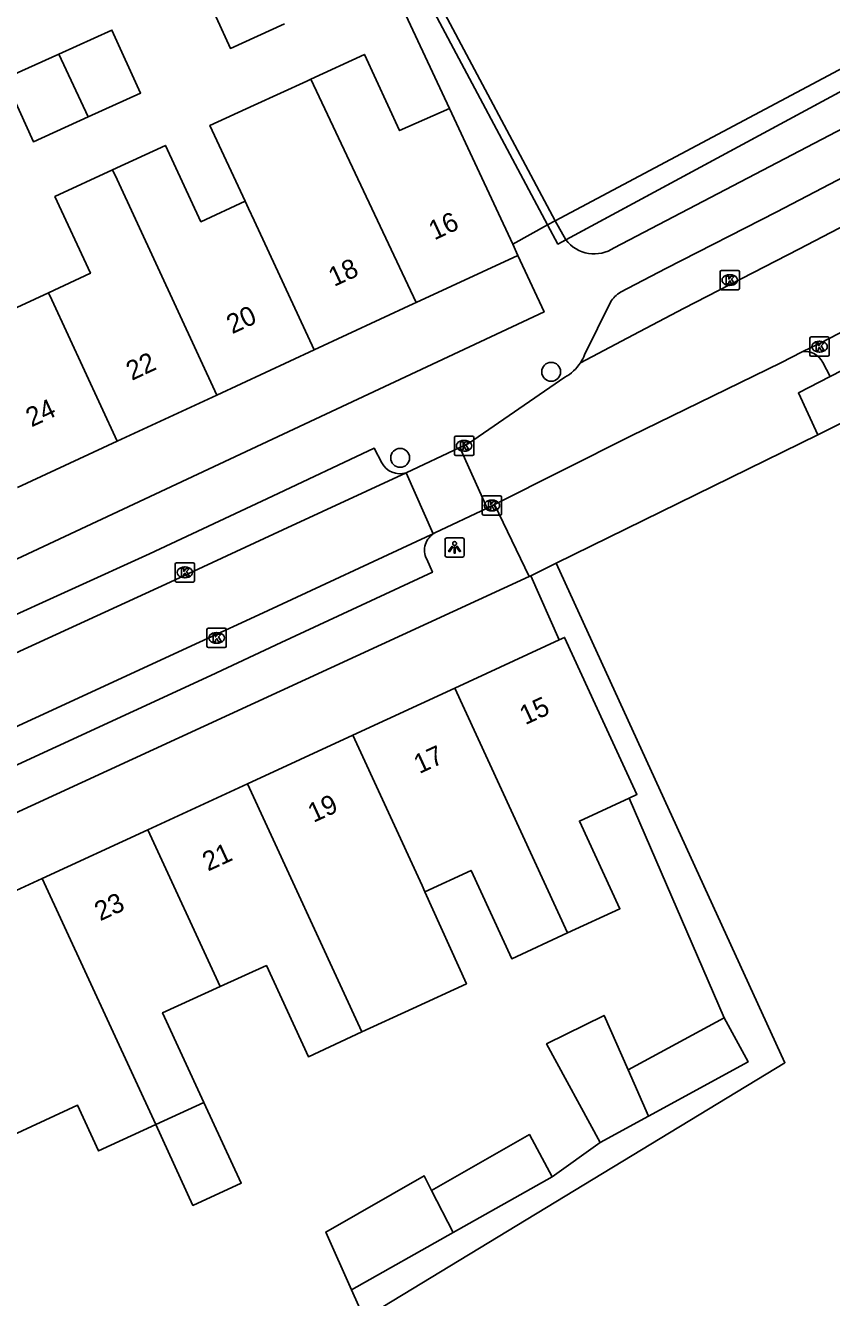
# Model space of a CAD drawing. Extents: x 159265 to 160143, y 383413 to 384319.
# Drawn here: x 159449.6 to 159491.4, y 384178.3 to 384244.2 of the extents above; entities that cross this region are included whole.
import ezdxf

# ---------------------------------------------------------------- set-up
doc = ezdxf.new("R2010")
doc.units = 0
for name, color, linetype in [('IMGEO_Boom', 7, 'Continuous'), ('IMGEO_Haag', 7, 'Continuous'), ('IMGEO_Kolk', 7, 'Continuous'), ('IMGEO_Lichtpunt', 7, 'Continuous'), ('IMGEO_Pand', 7, 'Continuous'), ('IMGEO_Pand_nummerreeks', 7, 'Continuous'), ('IMGEO_Pand_overbouw', 7, 'Continuous'), ('IMGEO_Rijbaan_lokaal_open', 7, 'Continuous'), ('IMGEO_Voetpad_open', 7, 'Continuous')]:
    doc.layers.add(name, color=color, linetype=linetype)

msp = doc.modelspace()

# ---------------------------------------------------------------- linework, layer by layer
at = {"layer": 'IMGEO_Boom'}
for centre in [(159476.832, 384226.238), (159469.003, 384221.78)]:
    msp.add_circle(centre, 0.489, dxfattribs=at)
at = {"layer": 'IMGEO_Haag'}
msp.add_lwpolyline([(159496.545, 384243.294), (159477.587, 384233.071)], dxfattribs=at)
at = {"layer": 'IMGEO_Kolk'}
for p, q in [((159485.589, 384230.564), (159485.589, 384231.416)), ((159485.664, 384231.49), (159486.516, 384231.49)), ((159486.077, 384231.27), (159486.102, 384231.27)), ((159486.59, 384231.416), (159486.59, 384230.564)), ((159486.516, 384230.49), (159485.664, 384230.49)), ((159486.1, 384230.71), (159486.075, 384230.71)), ((159490.239, 384227.116), (159490.239, 384227.968)), ((159490.314, 384228.042), (159491.166, 384228.042)), ((159490.727, 384227.822), (159490.752, 384227.822)), ((159491.24, 384227.968), (159491.24, 384227.116)), ((159490.75, 384227.262), (159490.725, 384227.262)), ((159491.166, 384227.042), (159490.314, 384227.042)), ((159471.82, 384221.979), (159471.82, 384222.831)), ((159471.895, 384222.905), (159472.747, 384222.905)), ((159472.308, 384222.685), (159472.333, 384222.685)), ((159472.821, 384222.831), (159472.821, 384221.979)), ((159472.747, 384221.905), (159471.895, 384221.905)), ((159472.331, 384222.125), (159472.306, 384222.125)), ((159473.335, 384219.811), (159474.187, 384219.811)), ((159473.26, 384218.885), (159473.26, 384219.737)), ((159473.748, 384219.591), (159473.773, 384219.591)), ((159474.261, 384219.737), (159474.261, 384218.885)), ((159474.187, 384218.811), (159473.335, 384218.811)), ((159473.771, 384219.031), (159473.746, 384219.031)), ((159457.346, 384215.419), (159457.346, 384216.271)), ((159457.421, 384216.345), (159458.273, 384216.345)), ((159457.834, 384216.125), (159457.859, 384216.125)), ((159458.347, 384216.271), (159458.347, 384215.419)), ((159458.273, 384215.345), (159457.421, 384215.345)), ((159457.857, 384215.565), (159457.832, 384215.565)), ((159458.993, 384212.026), (159458.993, 384212.878)), ((159459.068, 384212.952), (159459.92, 384212.952)), ((159459.481, 384212.732), (159459.506, 384212.732)), ((159459.994, 384212.878), (159459.994, 384212.026)), ((159459.92, 384211.952), (159459.068, 384211.952)), ((159459.504, 384212.172), (159459.479, 384212.172))]:
    msp.add_line(p, q, dxfattribs=at)
for points in [[(159485.589, 384230.564), (159485.589, 384231.416)], [(159485.664, 384231.49), (159486.516, 384231.49)], [(159485.91, 384231.19), (159486.033, 384231.19), (159486.033, 384231.039), (159486.163, 384231.19), (159486.327, 384231.19), (159486.181, 384231.039), (159486.334, 384230.79), (159486.182, 384230.79), (159486.097, 384230.954), (159486.033, 384230.887), (159486.033, 384230.79), (159485.91, 384230.79), (159485.91, 384231.19)], [(159486.59, 384231.416), (159486.59, 384230.564)], [(159486.516, 384230.49), (159485.664, 384230.49)], [(159490.239, 384227.116), (159490.239, 384227.968)], [(159490.314, 384228.042), (159491.166, 384228.042)], [(159490.56, 384227.742), (159490.683, 384227.742), (159490.683, 384227.591), (159490.813, 384227.742), (159490.977, 384227.742), (159490.831, 384227.591), (159490.984, 384227.342), (159490.832, 384227.342), (159490.747, 384227.506), (159490.683, 384227.439), (159490.683, 384227.342), (159490.56, 384227.342), (159490.56, 384227.742)], [(159491.24, 384227.968), (159491.24, 384227.116)], [(159491.166, 384227.042), (159490.314, 384227.042)], [(159471.82, 384221.979), (159471.82, 384222.831)], [(159471.895, 384222.905), (159472.747, 384222.905)], [(159472.141, 384222.605), (159472.264, 384222.605), (159472.264, 384222.454), (159472.394, 384222.605), (159472.558, 384222.605), (159472.412, 384222.454), (159472.565, 384222.205), (159472.413, 384222.205), (159472.328, 384222.369), (159472.264, 384222.302), (159472.264, 384222.205), (159472.141, 384222.205), (159472.141, 384222.605)], [(159472.821, 384222.831), (159472.821, 384221.979)], [(159472.747, 384221.905), (159471.895, 384221.905)], [(159473.335, 384219.811), (159474.187, 384219.811)], [(159473.26, 384218.885), (159473.26, 384219.737)], [(159473.581, 384219.511), (159473.704, 384219.511), (159473.704, 384219.36), (159473.834, 384219.511), (159473.998, 384219.511), (159473.852, 384219.36), (159474.005, 384219.111), (159473.853, 384219.111), (159473.768, 384219.275), (159473.704, 384219.208), (159473.704, 384219.111), (159473.581, 384219.111), (159473.581, 384219.511)], [(159474.261, 384219.737), (159474.261, 384218.885)], [(159474.187, 384218.811), (159473.335, 384218.811)], [(159457.346, 384215.419), (159457.346, 384216.271)], [(159457.421, 384216.345), (159458.273, 384216.345)], [(159457.667, 384216.045), (159457.79, 384216.045), (159457.79, 384215.894), (159457.92, 384216.045), (159458.084, 384216.045), (159457.938, 384215.894), (159458.091, 384215.645), (159457.939, 384215.645), (159457.854, 384215.809), (159457.79, 384215.742), (159457.79, 384215.645), (159457.667, 384215.645), (159457.667, 384216.045)], [(159458.347, 384216.271), (159458.347, 384215.419)], [(159458.273, 384215.345), (159457.421, 384215.345)], [(159458.993, 384212.026), (159458.993, 384212.878)], [(159459.068, 384212.952), (159459.92, 384212.952)], [(159459.314, 384212.652), (159459.437, 384212.652), (159459.437, 384212.501), (159459.567, 384212.652), (159459.731, 384212.652), (159459.585, 384212.501), (159459.738, 384212.252), (159459.586, 384212.252), (159459.501, 384212.416), (159459.437, 384212.349), (159459.437, 384212.252), (159459.314, 384212.252), (159459.314, 384212.652)], [(159459.994, 384212.878), (159459.994, 384212.026)], [(159459.92, 384211.952), (159459.068, 384211.952)]]:
    msp.add_lwpolyline(points, dxfattribs=at)
for centre, start, end in [((159485.666, 384231.414), 91.55205, 178.44795), ((159485.666, 384231.414), 91.55205, 178.44795), ((159486.514, 384231.414), 1.55205, 88.44795), ((159486.514, 384231.414), 1.55205, 88.44795), ((159485.666, 384230.566), 181.55205, 268.44795), ((159485.666, 384230.566), 181.55205, 268.44795), ((159486.514, 384230.566), 271.55205, 358.44795), ((159486.514, 384230.566), 271.55205, 358.44795), ((159490.316, 384227.966), 91.55205, 178.44795), ((159490.316, 384227.966), 91.55205, 178.44795), ((159491.164, 384227.966), 1.55205, 88.44795), ((159491.164, 384227.966), 1.55205, 88.44795), ((159490.316, 384227.118), 181.55205, 268.44795), ((159490.316, 384227.118), 181.55205, 268.44795), ((159491.164, 384227.118), 271.55205, 358.44795), ((159491.164, 384227.118), 271.55205, 358.44795), ((159471.897, 384222.829), 91.55205, 178.44795), ((159471.897, 384222.829), 91.55205, 178.44795), ((159472.745, 384222.829), 1.55205, 88.44795), ((159472.745, 384222.829), 1.55205, 88.44795), ((159471.897, 384221.981), 181.55205, 268.44795), ((159471.897, 384221.981), 181.55205, 268.44795), ((159472.745, 384221.981), 271.55205, 358.44795), ((159472.745, 384221.981), 271.55205, 358.44795), ((159473.337, 384219.735), 91.55205, 178.44795), ((159473.337, 384219.735), 91.55205, 178.44795), ((159474.185, 384219.735), 1.55205, 88.44795), ((159474.185, 384219.735), 1.55205, 88.44795), ((159473.337, 384218.887), 181.55205, 268.44795), ((159473.337, 384218.887), 181.55205, 268.44795), ((159474.185, 384218.887), 271.55205, 358.44795), ((159474.185, 384218.887), 271.55205, 358.44795), ((159457.423, 384216.269), 91.55205, 178.44795), ((159457.423, 384216.269), 91.55205, 178.44795), ((159458.271, 384216.269), 1.55205, 88.44795), ((159458.271, 384216.269), 1.55205, 88.44795), ((159457.423, 384215.421), 181.55205, 268.44795), ((159457.423, 384215.421), 181.55205, 268.44795), ((159458.271, 384215.421), 271.55205, 358.44795), ((159458.271, 384215.421), 271.55205, 358.44795), ((159459.07, 384212.876), 91.55205, 178.44795), ((159459.07, 384212.876), 91.55205, 178.44795), ((159459.918, 384212.876), 1.55205, 88.44795), ((159459.918, 384212.876), 1.55205, 88.44795), ((159459.07, 384212.028), 181.55205, 268.44795), ((159459.07, 384212.028), 181.55205, 268.44795), ((159459.918, 384212.028), 271.55205, 358.44795), ((159459.918, 384212.028), 271.55205, 358.44795)]:
    msp.add_arc(centre, 0.0765, start, end, dxfattribs=at)
for centre, major_axis, ratio, start_param, end_param in [((159486.076, 384230.99), (-0.387, 0.002), 0.722429, 4.712389, 7.853982), ((159486.101, 384230.99), (-0.39, 0.002), 0.717154, 1.570796, 4.712389), ((159490.726, 384227.542), (-0.387, 0.002), 0.722429, 4.712389, 7.853982), ((159490.751, 384227.542), (-0.39, 0.002), 0.717154, 1.570796, 4.712389), ((159472.307, 384222.405), (-0.387, 0.002), 0.722429, 4.712389, 7.853982), ((159472.332, 384222.405), (-0.39, 0.002), 0.717154, 1.570796, 4.712389), ((159473.747, 384219.311), (-0.387, 0.002), 0.722429, 4.712389, 7.853982), ((159473.772, 384219.311), (-0.39, 0.002), 0.717154, 1.570796, 4.712389), ((159457.833, 384215.845), (-0.387, 0.002), 0.722429, 4.712389, 7.853982), ((159457.858, 384215.845), (-0.39, 0.002), 0.717154, 1.570796, 4.712389), ((159459.48, 384212.452), (-0.387, 0.002), 0.722429, 4.712389, 7.853982), ((159459.505, 384212.452), (-0.39, 0.002), 0.717154, 1.570796, 4.712389)]:
    msp.add_ellipse(centre, major_axis=major_axis, ratio=ratio, start_param=start_param, end_param=end_param, dxfattribs=at)
at = {"layer": 'IMGEO_Lichtpunt'}
for p, q in [((159471.33, 384217.542), (159471.33, 384216.735)), ((159471.33, 384217.542), (159471.33, 384216.735)), ((159472.232, 384217.637), (159471.424, 384217.637)), ((159472.232, 384217.637), (159471.424, 384217.637)), ((159472.326, 384216.735), (159472.326, 384217.542)), ((159472.326, 384216.735), (159472.326, 384217.542)), ((159471.424, 384216.641), (159472.232, 384216.641)), ((159471.424, 384216.641), (159472.232, 384216.641))]:
    msp.add_line(p, q, dxfattribs=at)
for points in [[(159471.704, 384217.206), (159471.743, 384217.178), (159471.555, 384216.916), (159471.517, 384216.943), (159471.704, 384217.206)], [(159471.916, 384217.178), (159471.954, 384217.205), (159472.141, 384216.943), (159472.102, 384216.915), (159471.916, 384217.178)], [(159471.806, 384217.158), (159471.853, 384217.158), (159471.853, 384216.836), (159471.806, 384216.836), (159471.806, 384217.158)]]:
    msp.add_lwpolyline(points, dxfattribs=at)
msp.add_circle((159471.829, 384217.34), 0.0994, dxfattribs=at)
for centre, start, end in [((159471.424, 384217.542), 90, 180), ((159471.424, 384217.542), 90, 180), ((159472.232, 384217.542), 0, 90), ((159472.232, 384217.542), 0, 90), ((159471.424, 384216.735), 180, 270), ((159471.424, 384216.735), 180, 270), ((159472.232, 384216.735), 270, 0), ((159472.232, 384216.735), 270, 360)]:
    msp.add_arc(centre, 0.0946, start, end, dxfattribs=at)
at = {"layer": 'IMGEO_Pand'}
for points in [[(159463.013, 384244.261), (159460.208, 384242.99), (159458.726, 384246.259), (159461.479, 384247.507)], [(159477.039, 384234.058), (159470.912, 384245.571)], [(159496.073, 384244.188), (159477.039, 384234.058)], [(159451.317, 384242.698), (159454.069, 384243.945), (159455.551, 384240.676), (159452.828, 384239.442)], [(159452.828, 384239.442), (159449.999, 384238.16), (159448.517, 384241.429), (159451.317, 384242.698)], [(159451.317, 384242.698), (159452.828, 384239.442)], [(159464.374, 384241.393), (159467.151, 384242.681), (159468.98, 384238.739), (159471.56, 384239.877)], [(159460.976, 384235.082), (159459.143, 384239.003), (159461.437, 384240.053), (159464.173, 384241.301), (159464.299, 384241.358), (159464.374, 384241.393)], [(159464.374, 384241.393), (159469.837, 384229.824)], [(159471.56, 384239.877), (159473.004, 384236.805), (159474.84, 384232.846)], [(159454.1, 384236.699), (159456.841, 384237.971), (159458.676, 384234.015), (159460.976, 384235.082)], [(159454.1, 384236.699), (159451.112, 384235.313), (159452.953, 384231.344), (159450.777, 384230.335)], [(159459.51, 384225.034), (159454.334, 384236.194), (159454.1, 384236.699)], [(159464.542, 384227.368), (159461.442, 384234.074), (159461.151, 384234.703), (159460.976, 384235.082)], [(159443.768, 384231.919), (159446.586, 384233.226), (159448.432, 384229.247), (159450.777, 384230.335)], [(159474.84, 384232.846), (159475.108, 384232.269)], [(159469.837, 384229.824), (159475.108, 384232.269)], [(159450.777, 384230.335), (159450.945, 384229.973), (159454.347, 384222.639)], [(159464.542, 384227.368), (159469.682, 384229.752), (159469.837, 384229.824)], [(159459.51, 384225.034), (159464.542, 384227.368)], [(159454.347, 384222.639), (159459.51, 384225.034)], [(159454.347, 384222.639), (159449.182, 384220.245)], [(159471.834, 384209.85), (159477.246, 384212.345)], [(159477.246, 384212.345), (159477.527, 384212.475), (159479.62, 384207.935), (159481.28, 384204.339), (159480.873, 384204.15)], [(159466.549, 384207.412), (159471.834, 384209.85)], [(159477.687, 384197.169), (159471.834, 384209.85)], [(159461.09, 384204.895), (159466.549, 384207.412)], [(159466.549, 384207.412), (159470.143, 384199.623), (159470.291, 384199.303)], [(159455.923, 384202.512), (159461.09, 384204.895)], [(159461.09, 384204.895), (159467.026, 384192.033)], [(159480.873, 384204.15), (159478.3, 384202.958), (159480.394, 384198.417), (159477.687, 384197.169)], [(159450.452, 384199.989), (159455.923, 384202.512)], [(159459.673, 384194.386), (159455.923, 384202.512)], [(159477.687, 384197.169), (159474.787, 384195.832), (159472.679, 384200.404), (159470.291, 384199.303)], [(159456.337, 384187.235), (159453.38, 384185.872), (159452.291, 384188.234), (159449.407, 384186.905), (159446.166, 384185.411), (159443.791, 384190.561), (159441.698, 384195.101), (159441.994, 384195.238), (159442.191, 384194.81), (159445.124, 384196.162), (159444.923, 384196.598), (159444.603, 384197.292), (159450.452, 384199.989)], [(159450.452, 384199.989), (159456.337, 384187.235)], [(159470.291, 384199.303), (159472.442, 384194.53), (159469.664, 384193.249), (159467.026, 384192.033)], [(159467.026, 384192.033), (159464.252, 384190.754), (159462.074, 384195.477), (159459.673, 384194.386)], [(159459.673, 384194.386), (159456.694, 384193.032), (159458.836, 384188.387)], [(159480.825, 384190.066), (159479.577, 384192.893), (159476.596, 384191.412), (159479.376, 384186.308)], [(159485.791, 384192.771), (159480.825, 384190.066)], [(159481.881, 384187.673), (159487.038, 384190.482), (159485.791, 384192.771)], [(159481.881, 384187.673), (159480.825, 384190.066)], [(159458.836, 384188.387), (159456.337, 384187.235)], [(159456.337, 384187.235), (159458.268, 384183.05), (159460.766, 384184.201), (159458.836, 384188.387)], [(159479.376, 384186.308), (159481.881, 384187.673)], [(159470.634, 384183.82), (159475.707, 384186.72), (159476.887, 384184.525)], [(159466.489, 384178.666), (159465.15, 384181.665), (159470.243, 384184.582), (159470.634, 384183.82)], [(159471.753, 384181.639), (159476.887, 384184.525)], [(159470.634, 384183.82), (159471.753, 384181.639)], [(159466.489, 384178.666), (159471.753, 384181.639)]]:
    msp.add_lwpolyline(points, dxfattribs=at)
at = {"layer": 'IMGEO_Pand_overbouw'}
msp.add_lwpolyline([(159490.056, 384255.626), (159496.073, 384244.188), (159477.039, 384234.058), (159470.912, 384245.571), (159470.517, 384245.361), (159476.65, 384233.844), (159477.179, 384232.851), (159496.545, 384243.294), (159499.694, 384244.992), (159497.376, 384249.348), (159497.036, 384250), (159493.218, 384257.331)], close=True, dxfattribs=at)
at = {"layer": 'IMGEO_Rijbaan_lokaal_open'}
for points in [[(159517.47, 384247.014), (159514.26, 384245.379), (159508.001, 384242.108), (159499.189, 384237.553), (159489.666, 384232.587), (159483.719, 384229.541), (159481.4, 384228.311), (159478.346, 384226.706)], [(159489.842, 384227.268), (159490.802, 384227.734), (159494.471, 384229.638), (159503.682, 384234.438)], [(159473.89, 384219.371), (159480.983, 384222.924), (159488.742, 384226.699), (159489.842, 384227.268)], [(159477.548, 384225.952), (159472.539, 384222.519), (159472.092, 384222.31)], [(159469.317, 384221.008), (159472.092, 384222.31)], [(159472.092, 384222.31), (159473.51, 384219.181)], [(159447.581, 384210.982), (159456.855, 384215.239), (159462.918, 384218.05), (159469.317, 384221.008)], [(159470.723, 384217.848), (159469.317, 384221.008)], [(159473.51, 384219.181), (159470.808, 384217.887)], [(159473.51, 384219.181), (159473.89, 384219.371)], [(159470.723, 384217.848), (159470.602, 384217.793), (159461.9, 384213.745), (159458.611, 384212.225), (159441.592, 384204.385)], [(159470.808, 384217.887), (159470.723, 384217.848)]]:
    msp.add_lwpolyline(points, dxfattribs=at)
msp.add_arc((159476.287, 384228.086), 2.478, 300.58004, 326.1721, dxfattribs=at)
at = {"layer": 'IMGEO_Voetpad_open'}
for points in [[(159465.887, 384252.041), (159471.56, 384239.877)], [(159496.987, 384243.532), (159497.85, 384241.932), (159497.391, 384241.69), (159480.102, 384232.668)], [(159480.432, 384230.361), (159482.782, 384231.592), (159488.519, 384234.532), (159498.319, 384239.644)], [(159474.84, 384232.846), (159476.65, 384233.844)], [(159476.65, 384233.844), (159477.039, 384234.058)], [(159477.587, 384233.071), (159477.179, 384232.851), (159476.65, 384233.844)], [(159477.587, 384233.071), (159477.039, 384234.058)], [(159491.288, 384225.993), (159495.298, 384228.054), (159504.143, 384232.646), (159503.536, 384233.821)], [(159475.108, 384232.269), (159476.465, 384229.34), (159445.521, 384214.855), (159445.294, 384214.752)], [(159506.018, 384230.681), (159500, 384227.661), (159490.659, 384222.974)], [(159478.567, 384227.115), (159479.902, 384229.851)], [(159490.912, 384226.714), (159491.288, 384225.993)], [(159490.659, 384222.974), (159489.644, 384225.148), (159491.288, 384225.993)], [(159490.659, 384222.974), (159477.098, 384216.319)], [(159448.144, 384211.983), (159447.955, 384213.139), (159456.019, 384216.815), (159462.387, 384219.8), (159467.663, 384222.276), (159468.052, 384221.521)], [(159473.89, 384219.371), (159475.693, 384215.632)], [(159442.747, 384203.913), (159443.14, 384203.112), (159459.195, 384210.497), (159462.832, 384212.209), (159470.68, 384215.856), (159470.382, 384216.534)], [(159477.098, 384216.319), (159488.946, 384190.443), (159467.136, 384177.214), (159466.489, 384178.666)], [(159475.775, 384215.67), (159477.098, 384216.319)], [(159475.693, 384215.632), (159408.528, 384184.712), (159407.818, 384184.342)], [(159475.775, 384215.67), (159475.693, 384215.632)], [(159477.246, 384212.345), (159475.775, 384215.67)], [(159485.791, 384192.771), (159480.873, 384204.15)], [(159476.887, 384184.525), (159479.376, 384186.308)]]:
    msp.add_lwpolyline(points, dxfattribs=at)
for centre, radius, start, end in [((159479.06, 384234.214), 1.864, 217.80583, 303.98696), ((159481.227, 384229.004), 1.573, 120.3765, 147.42009), ((159476.295, 384228.078), 2.468, 326.2105, 337.02104), ((159490.021, 384226.303), 0.982, 24.76326, 100.49039), ((159468.987, 384222.011), 1.056, 207.65718, 288.19441), ((159471.262, 384217.001), 0.996, 117.10473, 207.94145)]:
    msp.add_arc(centre, radius, start, end, dxfattribs=at)

# ---------------------------------------------------------------- texts
at = {"layer": 'IMGEO_Pand_nummerreeks'}
for s, rotation, p in [('16', 24.88356, (159470.78, 384233.041)), ('18', 24.88356, (159465.583, 384230.63)), ('20', 24.88356, (159460.302, 384228.18)), ('22', 24.88464, (159455.096, 384225.764)), ('24', 24.88464, (159449.9, 384223.354)), ('15', 24.75751, (159475.489, 384207.923)), ('17', 24.75693, (159470.001, 384205.393)), ('19', 24.75693, (159464.514, 384202.862)), ('21', 24.75693, (159459.047, 384200.341)), ('23', 24.75693, (159453.457, 384197.763))]:
    msp.add_text(s, height=1, rotation=rotation, dxfattribs=at).set_placement(p)

doc.saveas('drawing.dxf')
